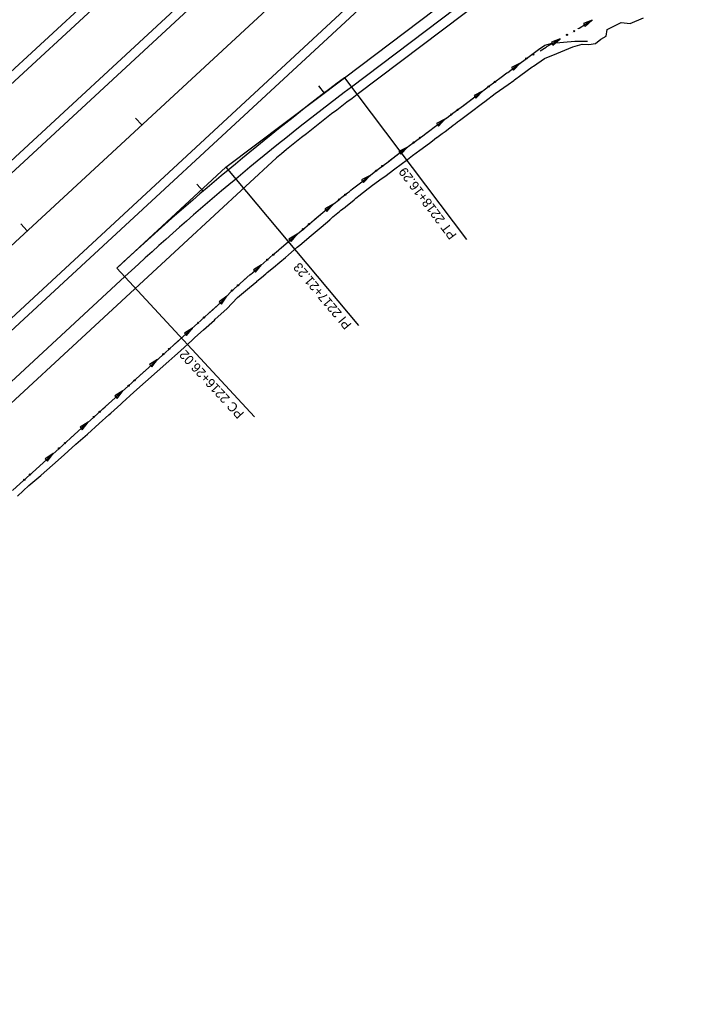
# Model space of a CAD drawing. Extents: x 1611108 to 1749517, y 619561 to 797725.
# Drawn here: x 1726595 to 1727029, y 770419 to 771050 of the extents above; entities that cross this region are included whole.
import ezdxf

# ---------------------------------------------------------------- set-up
doc = ezdxf.new("R2010")
doc.units = 0
for name, color, linetype in [('R_Ditch', 7, 'Continuous'), ('R_Horz Alg', 7, 'Continuous'), ('R_Horz Alg Annot', 7, 'Continuous'), ('R_Horz Alg Stationing', 7, 'Continuous'), ('R_Proposed Const Limits', 7, 'Continuous'), ('R_Proposed Road', 7, 'Continuous')]:
    doc.layers.add(name, color=color, linetype=linetype)

msp = doc.modelspace()

# ---------------------------------------------------------------- linework, layer by layer
at = {"layer": 'R_Ditch'}
for p, q in [((1726961.88, 771049.42), (1726956.17, 771047.3)), ((1726956.17, 771047.3), (1726957.24, 771045.47)), ((1726957.24, 771045.47), (1726961.88, 771049.42)), ((1726941.34, 771037.53), (1726935.63, 771035.41)), ((1726936.69, 771033.58), (1726941.34, 771037.53)), ((1726935.63, 771035.41), (1726936.69, 771033.58)), ((1726915.6, 771021.94), (1726910.15, 771019.2)), ((1726910.15, 771019.2), (1726911.42, 771017.5)), ((1726911.42, 771017.5), (1726915.6, 771021.94)), ((1726891.51, 771003.99), (1726886.07, 771001.25)), ((1726886.07, 771001.25), (1726887.33, 770999.55)), ((1726887.33, 770999.55), (1726891.51, 771003.99)), ((1726867.43, 770986.03), (1726861.99, 770983.3)), ((1726861.99, 770983.3), (1726863.25, 770981.6)), ((1726863.25, 770981.6), (1726867.43, 770986.03)), ((1726843.34, 770968.08), (1726837.9, 770965.34)), ((1726839.17, 770963.64), (1726843.34, 770968.08)), ((1726837.9, 770965.34), (1726839.17, 770963.64)), ((1726819.39, 770949.95), (1726813.99, 770947.14)), ((1726815.28, 770945.46), (1726819.39, 770949.95)), ((1726813.99, 770947.14), (1726815.28, 770945.46)), ((1726795.71, 770931.48), (1726790.35, 770928.57)), ((1726791.67, 770926.92), (1726795.71, 770931.48)), ((1726790.35, 770928.57), (1726791.67, 770926.92)), ((1726772.64, 770912.24), (1726767.39, 770909.16)), ((1726768.76, 770907.55), (1726772.64, 770912.24)), ((1726767.39, 770909.16), (1726768.76, 770907.55)), ((1726749.85, 770892.68), (1726744.62, 770889.55)), ((1726746.01, 770887.95), (1726749.85, 770892.68)), ((1726744.62, 770889.55), (1726746.01, 770887.95)), ((1726727.53, 770872.61), (1726722.65, 770868.96)), ((1726722.65, 770868.96), (1726724.19, 770867.51)), ((1726724.19, 770867.51), (1726727.53, 770872.61)), ((1726705.55, 770852.16), (1726700.38, 770848.92)), ((1726700.38, 770848.92), (1726701.8, 770847.35)), ((1726701.8, 770847.35), (1726705.55, 770852.16)), ((1726683.25, 770832.03), (1726678.08, 770828.8)), ((1726679.5, 770827.23), (1726683.25, 770832.03)), ((1726678.08, 770828.8), (1726679.5, 770827.23)), ((1726660.95, 770811.91), (1726655.78, 770808.68)), ((1726657.2, 770807.1), (1726660.95, 770811.91)), ((1726655.78, 770808.68), (1726657.2, 770807.1)), ((1726638.65, 770791.79), (1726633.48, 770788.55)), ((1726634.9, 770786.98), (1726638.65, 770791.79)), ((1726633.48, 770788.55), (1726634.9, 770786.98)), ((1726616.35, 770771.66), (1726611.18, 770768.43)), ((1726611.18, 770768.43), (1726612.6, 770766.86)), ((1726612.6, 770766.86), (1726616.35, 770771.66))]:
    msp.add_line(p, q, dxfattribs=at)
for points in [[(1726952.54, 771043.95), (1726952.83, 771044.11), (1726953.39, 771044.44), (1726957.56, 771046.89), (1726961.88, 771049.42)], [(1726928.39, 771029.95), (1726932.28, 771032.22), (1726932.84, 771032.55), (1726937.02, 771035), (1726941.34, 771037.53)], [(1726948.91, 771041.82), (1726948.94, 771041.84)], [(1726590.1, 770747.98), (1726597.53, 770754.68), (1726604.95, 770761.38), (1726605.21, 770761.61), (1726612.38, 770768.08), (1726619.8, 770774.78), (1726622.36, 770777.09), (1726627.22, 770781.48), (1726634.65, 770788.18), (1726642.07, 770794.88), (1726648.2, 770800.41), (1726649.5, 770801.58), (1726655.92, 770807.37), (1726656.92, 770808.28), (1726664.35, 770814.98), (1726671.77, 770821.68), (1726679.2, 770828.38), (1726686.62, 770835.08), (1726690.38, 770838.47), (1726694.05, 770841.78), (1726701.47, 770848.48), (1726703.34, 770850.17), (1726708.9, 770855.18), (1726715.81, 770861.42), (1726716.32, 770861.88), (1726723.75, 770868.58), (1726730.6, 770875.89), (1726738.13, 770882.49), (1726742.65, 770886.43), (1726742.78, 770886.55), (1726742.79, 770886.56), (1726745.67, 770889.06), (1726748.49, 770891.51), (1726749.38, 770892.28), (1726753.23, 770895.61), (1726757.18, 770899.01), (1726760.81, 770902.14), (1726762.73, 770903.78), (1726768.42, 770908.65), (1726769.98, 770909.98), (1726774.26, 770913.62), (1726776.04, 770915.13), (1726783.68, 770921.59), (1726789.22, 770926.25), (1726789.4, 770926.41), (1726789.42, 770926.43), (1726791.36, 770928.02), (1726795.7, 770931.47), (1726796.33, 770931.97), (1726799.19, 770934.23), (1726799.22, 770934.25), (1726799.5, 770934.47), (1726805.06, 770938.84), (1726806.25, 770939.77), (1726807.11, 770940.44), (1726807.18, 770940.5), (1726808.25, 770941.33), (1726814.22, 770945.97), (1726815.04, 770946.6), (1726816.87, 770948.02), (1726823, 770952.72), (1726824.56, 770953.92), (1726830.99, 770958.81), (1726839.02, 770964.85), (1726842.39, 770967.37), (1726847.08, 770970.87), (1726853.2, 770975.43), (1726855.14, 770976.88), (1726857.8, 770978.86), (1726857.83, 770978.88), (1726860.43, 770980.82), (1726861.43, 770981.57), (1726863.2, 770982.89), (1726866.35, 770985.23), (1726868.19, 770986.6), (1726868.46, 770986.8), (1726869.61, 770987.67), (1726871.27, 770988.9), (1726872.58, 770989.88), (1726879.33, 770994.91), (1726887.39, 771000.92), (1726888.77, 771001.94), (1726895.45, 771006.93), (1726903.52, 771012.94), (1726907.18, 771015.67), (1726907.7, 771016.06), (1726911.58, 771018.95), (1726918.87, 771024.38), (1726919.64, 771024.95), (1726927.3, 771030.66), (1726931.54, 771033.5), (1726936.12, 771034.76), (1726950.6, 771036.02), (1726958.91, 771035.97)], [(1726928.36, 771029.93), (1726928.39, 771029.95)], [(1726903.57, 771012.97), (1726907.18, 771015.67), (1726907.7, 771016.06), (1726911.58, 771018.95), (1726915.6, 771021.94)], [(1726903.54, 771012.95), (1726903.57, 771012.97)], [(1726879.48, 770995.02), (1726887.39, 771000.92), (1726888.77, 771001.94), (1726891.51, 771003.99)], [(1726879.45, 770995), (1726879.48, 770995.02)], [(1726855.4, 770977.07), (1726857.8, 770978.86), (1726857.83, 770978.88), (1726860.43, 770980.82), (1726861.43, 770981.57), (1726863.2, 770982.89), (1726866.35, 770985.23), (1726867.43, 770986.03)], [(1726855.37, 770977.05), (1726855.4, 770977.07)], [(1726831.35, 770959.08), (1726839.02, 770964.85), (1726842.39, 770967.37), (1726843.34, 770968.08)], [(1726831.32, 770959.05), (1726831.35, 770959.07)], [(1726807.53, 770940.77), (1726808.25, 770941.33), (1726814.22, 770945.97), (1726815.04, 770946.6), (1726816.87, 770948.02), (1726819.39, 770949.95)], [(1726807.5, 770940.75), (1726807.53, 770940.77)], [(1726784.12, 770921.96), (1726789.22, 770926.25), (1726789.4, 770926.41), (1726789.42, 770926.43), (1726791.36, 770928.02), (1726795.7, 770931.47), (1726795.71, 770931.48)], [(1726784.09, 770921.94), (1726784.12, 770921.96)], [(1726761.24, 770902.5), (1726762.73, 770903.78), (1726768.42, 770908.65), (1726769.98, 770909.98), (1726772.64, 770912.24)], [(1726761.21, 770902.48), (1726761.24, 770902.5)], [(1726738.53, 770882.84), (1726742.65, 770886.43), (1726742.78, 770886.55), (1726742.79, 770886.56), (1726745.67, 770889.06), (1726748.49, 770891.51), (1726749.38, 770892.28), (1726749.85, 770892.68)], [(1726738.5, 770882.81), (1726738.53, 770882.84)], [(1726716.71, 770862.23), (1726723.75, 770868.58), (1726727.53, 770872.61)], [(1726716.68, 770862.21), (1726716.71, 770862.23)], [(1726694.41, 770842.11), (1726701.47, 770848.48), (1726703.34, 770850.17), (1726705.55, 770852.16)], [(1726694.38, 770842.08), (1726694.41, 770842.11)], [(1726672.11, 770821.98), (1726679.2, 770828.38), (1726683.25, 770832.03)], [(1726672.08, 770821.96), (1726672.11, 770821.98)], [(1726649.81, 770801.86), (1726655.92, 770807.37), (1726656.92, 770808.28), (1726660.95, 770811.91)], [(1726649.78, 770801.84), (1726649.81, 770801.86)], [(1726627.51, 770781.74), (1726634.65, 770788.18), (1726638.65, 770791.79)], [(1726627.48, 770781.71), (1726627.51, 770781.74)], [(1726605.21, 770761.61), (1726612.38, 770768.08), (1726616.35, 770771.66)], [(1726605.18, 770761.59), (1726605.21, 770761.61), (1726605.21, 770761.61)]]:
    msp.add_lwpolyline(points, dxfattribs=at)
for centre in [(1726945.64, 771040.09), (1726950.23, 771042.5), (1726919.59, 771024.96), (1726923.94, 771027.41), (1726895.5, 771007.01), (1726899.52, 771010), (1726871.42, 770989.06), (1726875.44, 770992.05), (1726851.35, 770974.1), (1726847.34, 770971.1), (1726827.33, 770956.07), (1726823.34, 770953.03), (1726803.56, 770937.71), (1726799.62, 770934.61), (1726780.26, 770918.75), (1726776.43, 770915.51), (1726757.4, 770899.25), (1726753.61, 770895.98), (1726734.73, 770879.56), (1726730.96, 770876.25), (1726709.24, 770855.54), (1726712.96, 770858.89), (1726686.94, 770835.41), (1726690.66, 770838.77), (1726668.36, 770818.65), (1726664.64, 770815.29), (1726646.06, 770798.52), (1726642.34, 770795.17), (1726623.76, 770778.4), (1726620.04, 770775.04), (1726597.74, 770754.92), (1726601.46, 770758.28)]:
    msp.add_circle(centre, 0.375, dxfattribs=at)
at = {"layer": 'R_Horz Alg'}
for p, q in [((1726122.78, 770473.69), (1737235.67, 780746.34)), ((1726803, 771012.63), (1727666.01, 771663.95))]:
    msp.add_line(p, q, dxfattribs=at)
msp.add_arc((1727953.49, 769488.19), 1909.86, 127.04167, 132.75, dxfattribs=at)
at = {"layer": 'R_Horz Alg Annot'}
for points in [[(1726657.07, 770890.64), (1726726.99, 770955.27), (1726803, 771012.63)], [(1726803, 771012.63), (1726881.31, 770908.87)], [(1726726.99, 770955.27), (1726811.9, 770853.72)], [(1726657.07, 770890.64), (1726745.32, 770795.18)]]:
    msp.add_lwpolyline(points, dxfattribs=at)
at = {"layer": 'R_Horz Alg Stationing'}
for points in [[(1726786.38, 771007.52), (1726790.03, 771002.76)], [(1726668.98, 770986.76), (1726673.05, 770982.35)], [(1726708.46, 770944.36), (1726712.36, 770939.8)], [(1726595.54, 770918.88), (1726599.62, 770914.47)]]:
    msp.add_lwpolyline(points, dxfattribs=at)
at = {"layer": 'R_Proposed Const Limits'}
for points in [[(1726959.56, 771033.84), (1726963.97, 771034.51), (1726967.46, 771037.38), (1726970.86, 771039.33), (1726971.49, 771043.58), (1726980.34, 771048.11), (1726986.06, 771047.46), (1726994.68, 771051.05)], [(1726593.38, 770744.44), (1726600.76, 770751.18), (1726608.36, 770757.69), (1726608.62, 770757.92), (1726615.82, 770764.35), (1726623.29, 770771.01), (1726625.86, 770773.3), (1726630.75, 770777.67), (1726638.32, 770784.21), (1726645.72, 770790.94), (1726651.85, 770796.46), (1726653.15, 770797.62), (1726659.59, 770803.4), (1726660.6, 770804.31), (1726668.03, 770810.99), (1726675.52, 770817.63), (1726683, 770824.27), (1726690.46, 770830.93), (1726694.23, 770834.31), (1726697.88, 770837.63), (1726705.28, 770844.35), (1726707.15, 770846.04), (1726712.7, 770851.06), (1726719.62, 770857.3), (1726720.12, 770857.76), (1726727.58, 770864.43), (1726734.52, 770871.66), (1726742.14, 770878.14), (1726746.73, 770882.02), (1726746.87, 770882.13), (1726746.88, 770882.14), (1726749.79, 770884.6), (1726752.66, 770887.01), (1726753.56, 770887.76), (1726757.45, 770891.05), (1726761.47, 770894.37), (1726765.11, 770897.48), (1726767.03, 770899.12), (1726772.75, 770903.96), (1726774.33, 770905.27), (1726778.67, 770908.86), (1726780.47, 770910.34), (1726788.09, 770916.83), (1726793.53, 770921.58), (1726793.72, 770921.74), (1726793.74, 770921.76), (1726795.65, 770923.38), (1726799.92, 770926.9), (1726800.54, 770927.41), (1726803.36, 770929.71), (1726803.39, 770929.73), (1726803.67, 770929.96), (1726809.16, 770934.41), (1726810.33, 770935.36), (1726811.18, 770936.04), (1726811.25, 770936.09), (1726812.31, 770936.95), (1726818.27, 770941.6), (1726819.08, 770942.23), (1726820.92, 770943.65), (1726827.22, 770948.16), (1726828.79, 770949.34), (1726835.26, 770954.19), (1726843.32, 770960.2), (1726846.7, 770962.7), (1726851.4, 770966.19), (1726857.5, 770970.77), (1726859.44, 770972.22), (1726862.1, 770974.21), (1726862.13, 770974.23), (1726864.72, 770976.18), (1726865.72, 770976.93), (1726867.49, 770978.25), (1726870.63, 770980.6), (1726872.46, 770981.98), (1726872.73, 770982.18), (1726873.89, 770983.05), (1726875.53, 770984.28), (1726876.84, 770985.26), (1726883.57, 770990.32), (1726891.59, 770996.37), (1726892.96, 770997.4), (1726899.64, 771002.4), (1726907.88, 771008.21), (1726911.58, 771010.91), (1726912.1, 771011.3), (1726916, 771014.16), (1726923.33, 771019.55), (1726924.11, 771020.12), (1726931.34, 771024.95), (1726939.07, 771028.14), (1726949.48, 771032.44), (1726955.43, 771034.07), (1726959.56, 771033.84)]]:
    msp.add_lwpolyline(points, dxfattribs=at)
at = {"layer": 'R_Proposed Road'}
for p, q in [((1726095.63, 770503.06), (1728041.11, 772301.44)), ((1726099.71, 770498.66), (1728045.18, 772297.04)), ((1726145.86, 770448.72), (1728091.34, 772247.1)), ((1726149.94, 770444.32), (1728095.41, 772242.7)), ((1727670.53, 771657.96), (1726807.51, 771006.65)), ((1727674.14, 771653.17), (1726811.13, 771001.86)), ((1726309.35, 770757.81), (1726778.01, 771191.04)), ((1726313.42, 770753.41), (1726782.08, 771186.64)), ((1726173.02, 770419.35), (1726759.35, 770961.35)), ((1726166.23, 770426.69), (1726662.16, 770885.13))]:
    msp.add_line(p, q, dxfattribs=at)
for radius, end in [(1902.36, 132.75), (1896.36, 129.02794)]:
    msp.add_arc((1727953.49, 769488.19), radius, 127.04167, end, dxfattribs=at)

# ---------------------------------------------------------------- texts
at = {"layer": 'R_Horz Alg Annot'}
for s, rotation, p in [('PT 2218+16.29', 127.04167, (1726875.3, 770911.85)), ('PI 2217+21.23', 129.89583, (1726807.95, 770854.46)), ('PC 2216+26.02', 132.75, (1726739.04, 770797.55))]:
    msp.add_text(s, height=6, rotation=rotation, dxfattribs=at).set_placement(p)

doc.saveas('drawing.dxf')
